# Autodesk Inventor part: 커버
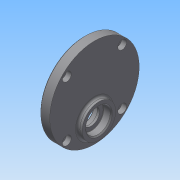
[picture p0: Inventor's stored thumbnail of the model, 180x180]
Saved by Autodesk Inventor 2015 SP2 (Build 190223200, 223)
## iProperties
Created: 2015-06
Part Number: 커버
Material: 일반
Document SubType Name: Modeling
Designer: AMC
Density: 1 g/cm^3
Appearance: 기본값
Author: AMC
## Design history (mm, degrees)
sketch "스케치1"
  geometry: C1 r 40 at (0, 0); 1 further point
  constraints: 1 centre point, 1 coincident
  dimensions: "d0" = 80 diameter of C1
extrude "돌출1" new body sketch "스케치1" distance "d1" = 9; taper "d2" = 0 deg
sketch "스케치2"
  geometry: C1 r 15 at (20, 0); 1 further point
  constraints: 1 centre point, 1 horizontal alignment
  dimensions: "d3" = 30 diameter of C1; "d4" = 20 distance of point (0, 0) C1.centre
extrude "돌출2" join sketch "스케치2" distance "d5" = 4; taper "d6" = 0 deg
sketch "스케치3"
  geometry: C1 r 14 at (11, 0); C2 r 15 at (-20, 0) reference; C3 r 14 at (-20, 0); 1 further point
  constraints: 2 centre point, 1 coincident, 1 horizontal alignment
  dimensions: "d7" = 28 diameter of C1; "d8" = 28 diameter of C3; "d9" = 11 distance of point (0, 0) C1.centre
extrude "돌출3" join sketch "스케치3" distance "d10" = 3; taper "d11" = 0 deg
sketch "스케치4" dims "d13" = 70
  geometry: L1 (0, 0)-(-28.284, 28.284); L2 (0, 0)-(0, 40); C1 r 4 at (-24.749, 24.749); A1 r 40 centre (0, 0) between (-28.284, 28.284) and (0, 40) reference; A2 r 40 centre (0, 0) between (-28.284, 28.284) and (0, 40) reference; 2 further points
  constraints: 4 end point, 4 point on circle, 1 centre point, 1 coincident, 1 point on line, 1 vertical, 3 other
  dimensions: "d12" = 45 deg angle of L2 L1; "d14" = 8 diameter of C1
extrude "돌출4" cut sketch "스케치4" distance "d15" = 4.4; taper "d16" = 0 deg
sketch "스케치5"
  geometry: C1 r 4 at (0, 0) reference; C2 r 2.25 at (0, 0); 1 further point
  constraints: 1 centre point, 1 coincident
  dimensions: "d17" = 4.5 diameter of C2
extrude "돌출5" cut sketch "스케치5" stored distance "d18" = 4.4; taper "d19" = 0 deg
fillet "모깎기1" dims "d23" = 2
chamfer "모따기1" distance "d24" = 1; stored, may be unused: second distance "d25" = 2, angle "d26" = 45 deg
sketch "스케치6"
  geometry: L1 (3, -3)-(3, 25) reference; L2 (3, 22)-(-4, 22); L3 (-4, 22)-(-4, 20); L4 (-4, 20)-(-5, 20); L5 (-5, 20)-(-5, 11); L6 (-5, 11)-(3, 11); 1 further point
  constraints: 10 end point, 4 perpendicular, 1 horizontal, 1 midpoint, 1 point on line
  dimensions: "d28" = 11 vertical distance of point (0, 0) L6.end; "d29" = 22 diameter of L2 L6; "d30" = 18 diameter of L4 L6; "d31" = 7 distance of L2.start L2.end; "d32" = 1 distance of L3.end L4.end
revolve "회전1" sketch "스케치6" stored, may be unused: angle "d33" = 90 deg
chamfer "모따기2" distance "d34" = 1; stored, may be unused: second distance "d35" = 2, angle "d36" = 45 deg
fillet "모깎기2" dims "d37" = 2
sketch "스케치7"
  geometry: L1 (-13, -5)-(-13, -35) reference; L2 (3, -34)-(3, -6) reference; L3 (-13, -9)-(-6, -9); L4 (-6, -9)-(-6, -12.5); L5 (-6, -12.5)-(-4, -12.5); L6 (-4, -12.5)-(-4, -9); L7 (-4, -9)-(3, -9); L8 (3, -9)-(3, -20); L9 (3, -20)-(-13, -20); L10 (-13, -9)-(-13, -20); 1 further point
  constraints: 16 end point, 4 perpendicular, 4 point on line, 2 midpoint, 1 horizontal
  dimensions: "d38" = 22 diameter of L7 L9; "d39" = 2 distance of L4.end L5.end; "d40" = 7 distance of L3.start L3.end; "d41" = 15 diameter of L5 L9
revolve "회전2" sketch "스케치7" stored, may be unused: angle "d42" = 90 deg
chamfer "모따기3" distance "d43" = 1; stored, may be unused: second distance "d44" = 2, angle "d45" = 45 deg
fillet "모깎기3" dims "d46" = 0.3
node "솔리드1"
pattern_circular "원형 패턴1" dims angle "d21" = 360 deg
node "투영된 루프1"
